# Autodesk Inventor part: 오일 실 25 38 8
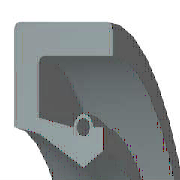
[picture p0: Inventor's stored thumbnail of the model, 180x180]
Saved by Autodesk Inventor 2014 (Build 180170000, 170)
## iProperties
IsCustomPart: 1
Created: 2012-02
Part Number: 오일 실 25 38 8
Material: 고무
Description: 오일-실
Document SubType Name: Modeling
Standard: KS B 2804
Designer: mduedu
Standards Organization: KS
Language: ko-KR
Size Designation: S - 25 38 8
Categories: <MemberInstance><Categories><Category DisplayName="샤프트 부품" InternalName="7f7aeb1f-a693-4053-b835-cee3144e0d98" Mnemonic="SHFT"><Category DisplayName="실링" Intern
Density: 0.93 g/cm^3
Appearance: 고무 - 검은색 - 버전 1.1
Author: mduedu
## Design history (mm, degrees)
revolve "본체" stored, may be unused: angle "d17" = 90 deg
revolve "스프링1" stored, may be unused: angle "d18" = 90 deg
body "Solid1"
sketch "스케치1"
  geometry: L1 (0, 19)-(8, 19); L2 (8, 19)-(8, 17.75); L3 (8, 17.75)-(1.75, 17.75); L4 (0, 19)-(0, 14.6); L5 (0, 14.6)-(1.75, 14.25); L6 (1.75, 14.25)-(4.9, 12.5); L7 (4.9, 12.5)-(0, 12.5); L8 (6.3, 13.375)-(6.3, 14.6); L9 (0, 0)-(9.586, 0) reference; L10 (4.9, 12.5)-(6.3, 13.375); L11 (0, 18)-(0, -3) reference; L12 (-1.917, 0)-(11.503, 0) reference; L13 (4.2, 14.6)-(1.75, 15.09); L14 (1.75, 15.09)-(1.75, 17.75); L15 (6.3, 14.6)-(5.6, 14.6); C1 r 0.455 at (4.9, 14.6); A1 r 0.7 centre (4.9, 14.6) between (5.6, 14.6) and (4.2, 14.6)
  constraints: 26 end point, 5 horizontal alignment, 4 perpendicular, 2 centre point, 2 collinear, 2 horizontal, 2 parallel, 2 point on circle, 2 point on line, 2 vertical alignment, 1 coincident
  dimensions: "d0" = 38 diameter of L1 L9 (= SD2); "d1" = 26.75 diameter of L8.start L9 (= ABDM); "d2" = 1.25 distance of L1.end L2.end (computed from SD); "d3" = 0.91 diameter of C1 (= SPDI); "d4" = 1.4 diameter of A1 (= SPDA); "d5" = 25 diameter of L6.end L9 (= NND); "d6" = 28.5 diameter of L5.end L9 (= TKDM); "d7" = 29.2 diameter of L4.end L9 (= HLDM); "d8" = 4.9 distance from line of C1.centre L4 (= SPDST); "d9" = 6.3 distance between parallel lines of L8 L4 (= SDI); "d10" = 8 distance between parallel lines of L2 L4 (= SWDT); "d12" = 1.75 distance between parallel lines of L14 L4 (= SD)
fillet "모깎기1" dims "d11" = 0.5 (= RR)
other parameters: "SD2" = 38 [user parameter; used in 1 equation term], "SWDT" = 8 [user parameter; used in 1 equation term], "RR" = 0.5 [user parameter; used in 1 equation term], "SD" = 1.75 [user parameter; used in 2 equation terms], "NND" = 25 [user parameter; used in 1 equation term], "SPDA" = 1.4 [user parameter; used in 1 equation term], "SPDI" = 0.91 [user parameter; used in 1 equation term], "TKDM" = 28.5 [user parameter; used in 1 equation term], "HLDM" = 29.2 [user parameter; used in 1 equation term], "ABDM" = 26.75 [user parameter; used in 1 equation term], "SDI" = 6.3 [user parameter; used in 1 equation term], "SPDST" = 4.9 [user parameter; used in 1 equation term], "d13" = 0, "d14" = 0, "d15" = 0, "LAB" = 0.35 [user parameter]
